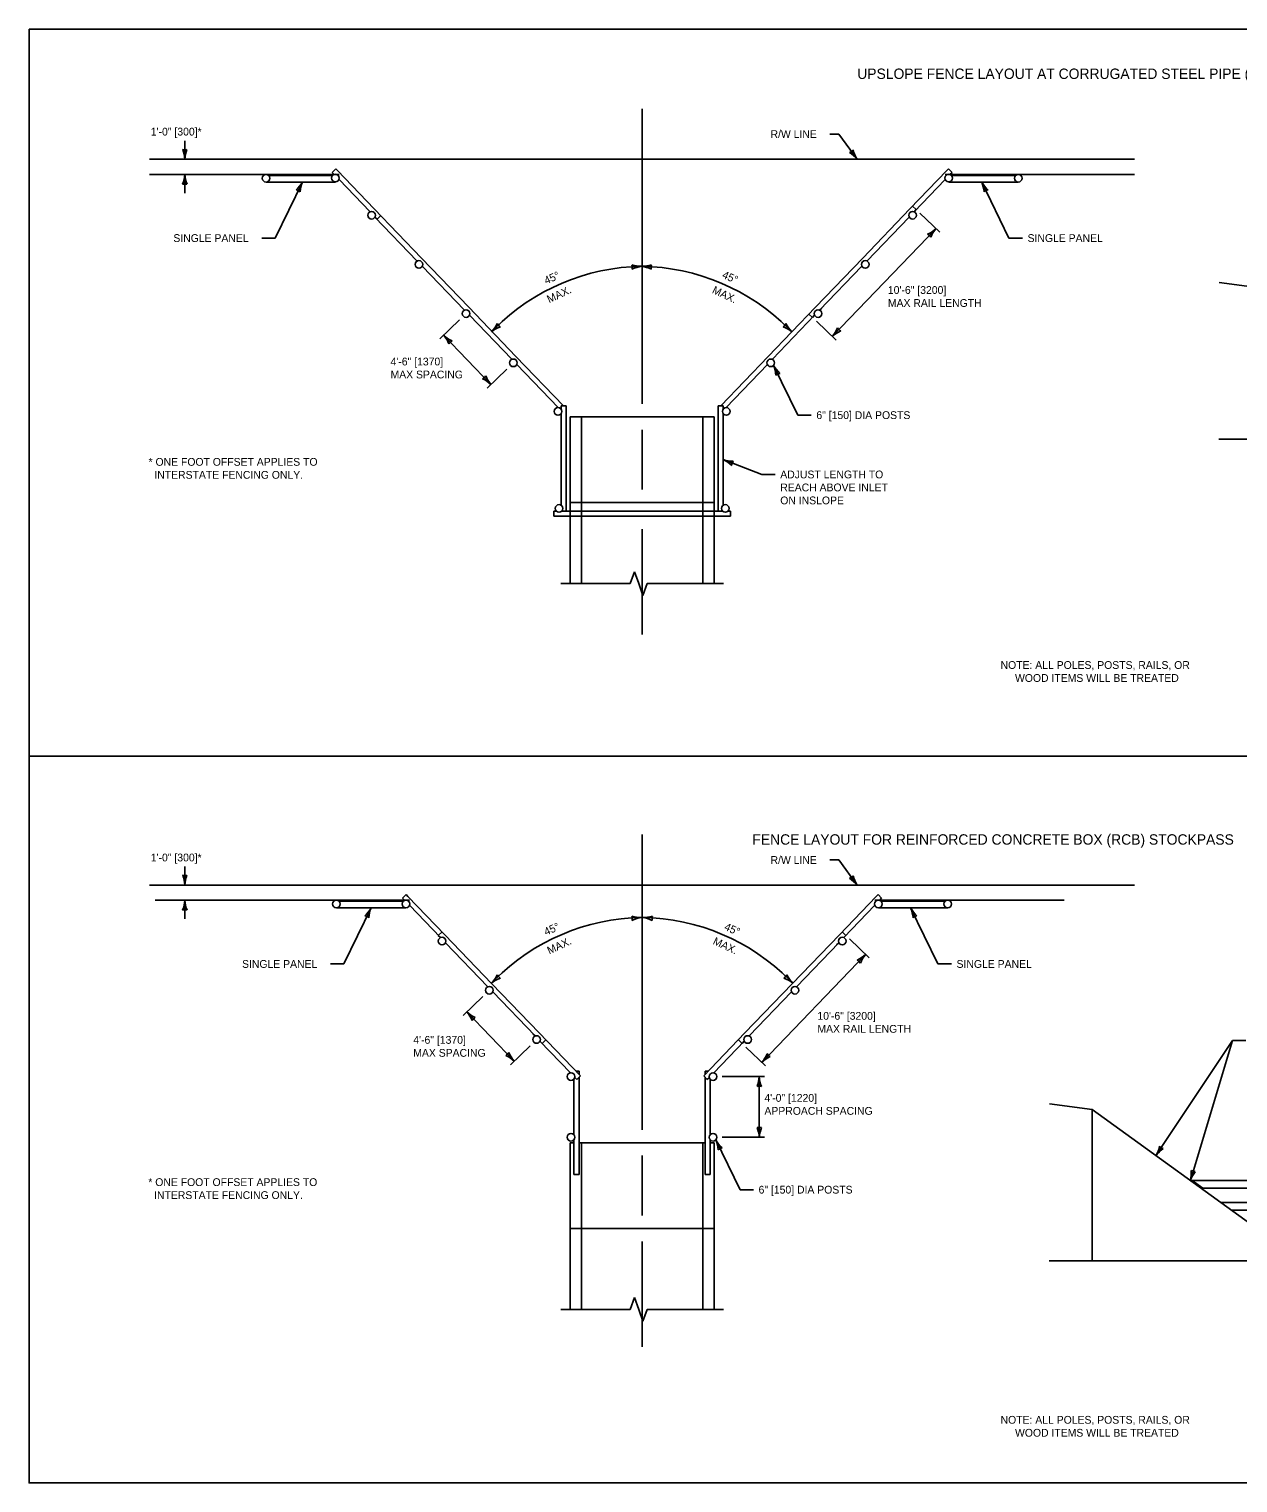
# Model space of a CAD drawing. Extents: x 49991 to 50288, y 49919 to 50011.
# Drawn here: x 49999.38 to 50008.7, y 49987.8 to 49999 of the extents above; entities that cross this region are included whole.
import ezdxf

# ---------------------------------------------------------------- set-up
doc = ezdxf.new("R2010")
doc.units = 0
for name, color, linetype in [('Level 1', 7, 'Continuous'), ('Level 2', 7, 'Continuous'), ('Level 3', 7, 'Continuous'), ('Level 5', 7, 'Continuous'), ('Level 6', 7, 'Continuous'), ('Level 7', 7, 'Continuous')]:
    doc.layers.add(name, color=color, linetype=linetype)

msp = doc.modelspace()

# ---------------------------------------------------------------- linework, layer by layer
at = {"layer": 'Level 1'}
for p, q in [((50000.311, 49997.996), (50007.9, 49997.996)), ((50000.311, 49997.879), (50001.771, 49997.879)), ((50001.209, 49997.821), (50001.743, 49997.821)), ((50001.228, 49997.872), (50001.723, 49997.872)), ((50007.9, 49997.879), (50006.441, 49997.879)), ((50006.441, 49997.879), (50006.441, 49997.879)), ((50007.003, 49997.821), (50006.468, 49997.821)), ((50006.983, 49997.872), (50006.488, 49997.872)), ((50003.639, 49996.011), (50003.551, 49996.011)), ((50003.551, 49996.011), (50003.551, 49995.975)), ((50003.639, 49996.011), (50003.639, 49994.727)), ((50003.639, 49996.011), (50004.573, 49996.011)), ((50004.573, 49996.011), (50004.573, 49994.727)), ((50004.573, 49996.011), (50004.66, 49996.011)), ((50004.66, 49996.011), (50004.66, 49995.975)), ((50003.551, 49995.975), (50003.551, 49994.727)), ((50004.66, 49995.975), (50004.66, 49994.727)), ((50010.401, 49995.839), (50008.548, 49995.839)), ((50003.551, 49995.351), (50004.66, 49995.351)), ((49999.384, 49993.399), (50016.75, 49993.399)), ((50000.311, 49992.404), (50007.9, 49992.404)), ((50000.356, 49992.288), (50002.313, 49992.288)), ((50001.751, 49992.229), (50002.286, 49992.229)), ((50001.771, 49992.281), (50002.266, 49992.281)), ((50002.313, 49992.288), (50002.313, 49992.288)), ((50007.358, 49992.288), (50005.898, 49992.288)), ((50005.898, 49992.288), (50005.898, 49992.288)), ((50006.46, 49992.229), (50005.926, 49992.229)), ((50006.441, 49992.281), (50005.945, 49992.281)), ((50008.916, 49989.704), (50007.573, 49990.676)), ((50007.573, 49990.676), (50007.573, 49989.511)), ((50003.551, 49990.42), (50003.551, 49990.383)), ((50003.551, 49990.42), (50003.551, 49990.383)), ((50003.581, 49990.42), (50003.551, 49990.42)), ((50003.581, 49990.42), (50003.551, 49990.42)), ((50003.639, 49990.42), (50003.62, 49990.42)), ((50003.639, 49990.42), (50003.62, 49990.42)), ((50003.639, 49990.42), (50003.639, 49989.135)), ((50003.639, 49990.42), (50004.573, 49990.42)), ((50004.573, 49990.42), (50004.573, 49989.135)), ((50004.573, 49990.42), (50004.591, 49990.42)), ((50004.631, 49990.42), (50004.66, 49990.42)), ((50004.66, 49990.42), (50004.66, 49990.383)), ((50003.551, 49990.383), (50003.551, 49989.135)), ((50004.66, 49990.383), (50004.66, 49989.135)), ((50003.551, 49989.759), (50004.66, 49989.759)), ((50009.095, 49989.511), (50007.242, 49989.511))]:
    msp.add_line(p, q, dxfattribs=at)
msp.add_lwpolyline([(49999.384, 49998.999), (50016.75, 49998.999), (50016.75, 49987.799), (49999.384, 49987.799)], close=True, dxfattribs=at)
msp.add_lwpolyline([(49999.384, 49998.999), (50016.75, 49998.999), (50016.75, 49987.799), (49999.384, 49987.799)], close=True, dxfattribs=at)
at = {"layer": 'Level 3'}
for p, q in [((50000.583, 49997.996), (50000.583, 49998.139)), ((50005.622, 49998.19), (50005.553, 49998.19)), ((50005.762, 49997.996), (50005.622, 49998.19)), ((50000.583, 49997.736), (50000.583, 49997.879)), ((50001.49, 49997.821), (50001.279, 49997.389)), ((50006.722, 49997.821), (50006.932, 49997.389)), ((50006.245, 49997.582), (50006.399, 49997.435)), ((50001.279, 49997.389), (50001.176, 49997.389)), ((50005.571, 49996.631), (50006.37, 49997.462)), ((50006.932, 49997.389), (50007.035, 49997.389)), ((50002.7, 49996.759), (50002.548, 49996.613)), ((50005.448, 49996.749), (50005.6, 49996.603)), ((50002.941, 49996.262), (50002.577, 49996.641)), ((50003.064, 49996.38), (50002.912, 49996.234)), ((50005.119, 49996.408), (50005.305, 49996.025)), ((50005.305, 49996.025), (50005.408, 49996.025)), ((50004.731, 49995.682), (50005.027, 49995.568)), ((50005.027, 49995.568), (50005.13, 49995.568)), ((50000.583, 49992.404), (50000.583, 49992.547)), ((50005.622, 49992.598), (50005.553, 49992.598)), ((50005.622, 49992.598), (50005.553, 49992.598)), ((50005.762, 49992.404), (50005.622, 49992.598)), ((50005.762, 49992.404), (50005.622, 49992.598)), ((50000.583, 49992.145), (50000.583, 49992.288)), ((50002.019, 49992.229), (50001.808, 49991.797)), ((50006.174, 49992.229), (50006.385, 49991.797)), ((50005.703, 49991.99), (50005.856, 49991.843)), ((50005.028, 49991.039), (50005.827, 49991.871)), ((50001.808, 49991.797), (50001.705, 49991.797)), ((50006.385, 49991.797), (50006.488, 49991.797)), ((50002.879, 49991.546), (50002.727, 49991.4)), ((50003.12, 49991.049), (50002.756, 49991.428)), ((50008.064, 49990.321), (50008.653, 49991.206)), ((50008.329, 49990.129), (50008.653, 49991.206)), ((50008.653, 49991.206), (50008.756, 49991.206)), ((50003.243, 49991.167), (50003.091, 49991.021)), ((50004.905, 49991.157), (50005.057, 49991.011)), ((50004.723, 49990.929), (50005.048, 49990.929)), ((50005.008, 49990.462), (50005.008, 49990.929)), ((50004.674, 49990.441), (50004.86, 49990.058)), ((50004.723, 49990.462), (50005.048, 49990.462)), ((50004.86, 49990.058), (50004.963, 49990.058))]:
    msp.add_line(p, q, dxfattribs=at)
for centre, radius, start, end in [((50000.583, 49998.124), 0.0548, 252.1388, 287.8612), ((50000.351, 49997.985), 0.233, 2.8273, 22.0772), ((50000.805, 49997.987), 0.222, 157.456, 177.6395), ((50005.687, 49998.1), 0.0548, 287.6554, 323.3778), ((50005.579, 49997.852), 0.233, 38.3439, 57.5938), ((50005.948, 49998.118), 0.222, 192.9726, 213.1561), ((50000.361, 49997.889), 0.222, 337.456, 357.6395), ((50000.583, 49997.751), 0.0548, 72.1388, 107.8612), ((50000.816, 49997.891), 0.233, 182.8273, 202.0772), ((50001.285, 49997.933), 0.233, 311.9873, 331.2371), ((50001.693, 49997.732), 0.222, 156.4249, 176.6084), ((50006.518, 49997.732), 0.222, 3.3916, 23.5751), ((50006.926, 49997.933), 0.233, 208.7629, 228.0127), ((50001.434, 49997.706), 0.0548, 46.2033, 81.9256), ((50006.778, 49997.706), 0.0548, 98.0744, 133.7967), ((50006.21, 49997.632), 0.233, 294.0637, 313.3135), ((50006.281, 49997.37), 0.0548, 28.2797, 64.002), ((50006.536, 49997.315), 0.222, 138.5013, 158.6848), ((50004.129, 49995.534), 1.638, 90.9235, 135.0582), ((50003.975, 49997.162), 0.0548, 346.4057, 22.1281), ((50004.097, 49997.405), 0.233, 252.1897, 271.4396), ((50004.128, 49996.951), 0.222, 96.6274, 116.8109), ((50004.108, 49997.405), 0.233, 268.5604, 287.8103), ((50004.077, 49996.951), 0.222, 63.1891, 83.3726), ((50004.076, 49995.534), 1.638, 44.9418, 89.0765), ((50004.23, 49997.162), 0.0548, 157.8719, 193.5943), ((50002.79, 49996.826), 0.222, 314.3336, 334.5171), ((50003.093, 49996.486), 0.233, 109.8959, 129.1458), ((50003.041, 49996.753), 0.0548, 204.1119, 239.8343), ((50005.164, 49996.753), 0.0548, 300.1657, 335.8881), ((50005.112, 49996.486), 0.233, 50.8542, 70.1041), ((50005.414, 49996.826), 0.222, 205.4829, 225.6664), ((50005.404, 49996.778), 0.222, 318.5013, 338.6848), ((50005.66, 49996.723), 0.0548, 208.2797, 244.002), ((50002.411, 49996.493), 0.222, 21.3152, 41.4987), ((50002.737, 49996.81), 0.233, 226.6865, 245.9363), ((50002.666, 49996.548), 0.0548, 115.998, 151.7203), ((50005.731, 49996.461), 0.233, 114.0637, 133.3135), ((50004.915, 49996.319), 0.222, 3.3916, 23.5751), ((50005.323, 49996.52), 0.233, 208.7629, 228.0127), ((50005.175, 49996.292), 0.0548, 98.0744, 133.7967), ((50002.852, 49996.354), 0.0548, 295.998, 331.7203), ((50002.781, 49996.092), 0.233, 46.6865, 65.9363), ((50003.108, 49996.409), 0.222, 201.3152, 221.4987), ((50004.643, 49995.477), 0.222, 46.4346, 66.6181), ((50004.804, 49995.903), 0.233, 251.8059, 271.0558), ((50004.851, 49995.636), 0.0548, 141.1174, 176.8398), ((50000.583, 49992.533), 0.0548, 252.1388, 287.8612), ((50000.351, 49992.393), 0.233, 2.8273, 22.0772), ((50000.805, 49992.395), 0.222, 157.456, 177.6395), ((50005.687, 49992.509), 0.0548, 287.6554, 323.3778), ((50005.687, 49992.509), 0.0548, 287.6554, 323.3778), ((50005.579, 49992.26), 0.233, 38.3439, 57.5938), ((50005.579, 49992.26), 0.233, 38.3439, 57.5938), ((50005.948, 49992.526), 0.222, 192.9726, 213.1561), ((50005.948, 49992.526), 0.222, 192.9726, 213.1561), ((50000.361, 49992.297), 0.222, 337.456, 357.6395), ((50000.583, 49992.159), 0.0548, 72.1388, 107.8612), ((50000.816, 49992.299), 0.233, 182.8273, 202.0772), ((50001.814, 49992.341), 0.233, 311.9873, 331.2371), ((50002.222, 49992.14), 0.222, 156.4249, 176.6084), ((50005.971, 49992.14), 0.222, 3.3916, 23.5751), ((50006.379, 49992.341), 0.233, 208.7629, 228.0127), ((50001.962, 49992.114), 0.0548, 46.2033, 81.9256), ((50004.129, 49990.517), 1.638, 90.9235, 135.0582), ((50003.975, 49992.145), 0.0548, 346.4057, 22.1281), ((50004.097, 49992.388), 0.233, 252.1897, 271.4396), ((50004.128, 49991.934), 0.222, 96.6274, 116.8109), ((50004.115, 49992.388), 0.233, 268.5604, 287.8103), ((50004.083, 49990.517), 1.638, 44.9418, 89.0765), ((50004.083, 49991.934), 0.222, 63.1891, 83.3726), ((50004.237, 49992.145), 0.0548, 157.8719, 193.5943), ((50006.23, 49992.114), 0.0548, 98.0744, 133.7967), ((50005.667, 49992.04), 0.233, 294.0637, 313.3135), ((50005.994, 49991.723), 0.222, 138.5013, 158.6848), ((50005.738, 49991.778), 0.0548, 28.2797, 64.002), ((50002.79, 49991.809), 0.222, 314.3336, 334.5171), ((50003.093, 49991.469), 0.233, 109.8959, 129.1458), ((50003.041, 49991.736), 0.0548, 204.1119, 239.8343), ((50005.17, 49991.736), 0.0548, 300.1657, 335.8881), ((50005.119, 49991.469), 0.233, 50.8542, 70.1041), ((50005.421, 49991.809), 0.222, 205.4829, 225.6664), ((50002.589, 49991.28), 0.222, 21.3152, 41.4987), ((50002.916, 49991.597), 0.233, 226.6865, 245.9363), ((50002.845, 49991.335), 0.0548, 115.998, 151.7203), ((50003.031, 49991.141), 0.0548, 295.998, 331.7203), ((50002.96, 49990.879), 0.233, 46.6865, 65.9363), ((50003.286, 49991.196), 0.222, 201.3152, 221.4987), ((50004.862, 49991.186), 0.222, 318.5013, 338.6848), ((50005.188, 49990.87), 0.233, 114.0637, 133.3135), ((50005.117, 49991.132), 0.0548, 208.2797, 244.002), ((50004.786, 49990.938), 0.222, 337.456, 357.6395), ((50005.241, 49990.94), 0.233, 182.8273, 202.0772), ((50005.008, 49990.801), 0.0548, 72.1388, 107.8612), ((50005.008, 49990.59), 0.0548, 252.1388, 287.8612), ((50004.776, 49990.45), 0.233, 2.8273, 22.0772), ((50005.231, 49990.453), 0.222, 157.456, 177.6395), ((50004.47, 49990.352), 0.222, 3.3916, 23.5751), ((50004.878, 49990.553), 0.233, 208.7629, 228.0127), ((50004.73, 49990.326), 0.0548, 98.0744, 133.7967), ((50007.864, 49990.44), 0.233, 329.1652, 348.415), ((50008.244, 49990.19), 0.222, 123.7939, 143.9774), ((50008.135, 49990.427), 0.0548, 218.4767, 254.199), ((50008.103, 49990.185), 0.233, 346.0815, 5.3313), ((50008.539, 49990.056), 0.222, 140.7102, 160.8937), ((50008.366, 49990.252), 0.0548, 235.393, 271.1153)]:
    msp.add_arc(centre, radius, start, end, dxfattribs=at)
at = {"layer": 'Level 5'}
for p, q in [((50004.106, 49996.111), (50004.106, 49998.385)), ((50008.879, 49997.003), (50008.551, 49997.048)), ((50004.106, 49995.451), (50004.106, 49995.911)), ((50004.106, 49994.335), (50004.106, 49995.146)), ((50004.106, 49990.52), (50004.106, 49992.794)), ((50007.573, 49990.676), (50007.245, 49990.72)), ((50004.106, 49989.859), (50004.106, 49990.32)), ((50004.106, 49988.848), (50004.106, 49989.659))]:
    msp.add_line(p, q, dxfattribs=at)
at = {"layer": 'Level 6'}
for p, q in [((50004.015, 49994.727), (50004.048, 49994.818)), ((50004.08, 49994.727), (50004.048, 49994.818)), ((50003.48, 49994.727), (50004.015, 49994.727)), ((50004.112, 49994.636), (50004.08, 49994.727)), ((50004.112, 49994.636), (50004.145, 49994.727)), ((50004.732, 49994.727), (50004.145, 49994.727)), ((50004.015, 49989.135), (50004.048, 49989.227)), ((50004.08, 49989.135), (50004.048, 49989.227)), ((50003.48, 49989.135), (50004.015, 49989.135)), ((50004.112, 49989.044), (50004.08, 49989.135)), ((50004.112, 49989.044), (50004.145, 49989.135)), ((50004.732, 49989.135), (50004.145, 49989.135))]:
    msp.add_line(p, q, dxfattribs=at)
at = {"layer": 'Level 7'}
for p, q in [((50001.718, 49997.895), (50001.746, 49997.922)), ((50001.746, 49997.922), (50001.759, 49997.909)), ((50006.465, 49997.922), (50006.452, 49997.909)), ((50006.494, 49997.895), (50006.465, 49997.922)), ((50001.734, 49997.878), (50001.718, 49997.895)), ((50001.759, 49997.909), (50002.042, 49997.614)), ((50001.771, 49997.84), (50002.01, 49997.591)), ((50006.452, 49997.909), (50006.169, 49997.614)), ((50006.441, 49997.84), (50006.202, 49997.591)), ((50006.477, 49997.878), (50006.494, 49997.895)), ((50002.042, 49997.614), (50002.406, 49997.235)), ((50006.169, 49997.614), (50005.805, 49997.235)), ((50006.218, 49997.608), (50006.189, 49997.635)), ((50006.202, 49997.591), (50006.218, 49997.608)), ((50002.048, 49997.551), (50002.374, 49997.212)), ((50002.048, 49997.551), (50002.064, 49997.535)), ((50002.064, 49997.535), (50002.093, 49997.562)), ((50006.163, 49997.551), (50005.837, 49997.212)), ((50006.163, 49997.551), (50006.147, 49997.535)), ((50002.406, 49997.235), (50002.77, 49996.857)), ((50002.412, 49997.173), (50002.738, 49996.834)), ((50005.805, 49997.235), (50005.441, 49996.857)), ((50005.799, 49997.173), (50005.473, 49996.834)), ((50002.77, 49996.857), (50003.134, 49996.478)), ((50002.776, 49996.794), (50003.102, 49996.455)), ((50005.441, 49996.857), (50005.077, 49996.478)), ((50005.435, 49996.794), (50005.109, 49996.455)), ((50005.419, 49996.777), (50005.391, 49996.804)), ((50005.435, 49996.794), (50005.419, 49996.777)), ((50005.473, 49996.834), (50005.49, 49996.85)), ((50003.134, 49996.478), (50003.501, 49996.096)), ((50005.077, 49996.478), (50004.711, 49996.096)), ((50003.14, 49996.415), (50003.458, 49996.084)), ((50005.071, 49996.415), (50004.753, 49996.084)), ((50003.52, 49996.096), (50003.481, 49996.096)), ((50003.481, 49996.096), (50003.481, 49996.072)), ((50003.481, 49995.328), (50003.481, 49996.035)), ((50003.52, 49995.286), (50003.52, 49996.096)), ((50004.692, 49995.286), (50004.692, 49996.096)), ((50004.692, 49996.096), (50004.731, 49996.096)), ((50004.731, 49996.096), (50004.731, 49996.072)), ((50004.731, 49995.328), (50004.731, 49996.035)), ((50003.445, 49995.286), (50003.425, 49995.286)), ((50003.425, 49995.286), (50003.425, 49995.246)), ((50003.425, 49995.246), (50004.662, 49995.246)), ((50003.487, 49995.286), (50004.696, 49995.286)), ((50004.725, 49995.286), (50003.515, 49995.286)), ((50004.787, 49995.246), (50003.549, 49995.246)), ((50004.766, 49995.286), (50004.787, 49995.286)), ((50004.787, 49995.286), (50004.787, 49995.246)), ((50002.261, 49992.304), (50002.289, 49992.331)), ((50002.289, 49992.331), (50002.302, 49992.317)), ((50002.302, 49992.317), (50002.585, 49992.022)), ((50005.91, 49992.317), (50005.626, 49992.022)), ((50005.923, 49992.331), (50005.91, 49992.317)), ((50005.951, 49992.304), (50005.923, 49992.331)), ((50002.277, 49992.287), (50002.261, 49992.304)), ((50002.313, 49992.249), (50002.553, 49992)), ((50005.898, 49992.249), (50005.659, 49992)), ((50005.935, 49992.287), (50005.951, 49992.304)), ((50002.536, 49992.016), (50002.565, 49992.044)), ((50002.553, 49992), (50002.536, 49992.016)), ((50002.585, 49992.022), (50002.949, 49991.644)), ((50005.626, 49992.022), (50005.262, 49991.644)), ((50005.675, 49992.016), (50005.647, 49992.044)), ((50005.659, 49992), (50005.675, 49992.016)), ((50002.591, 49991.96), (50002.917, 49991.621)), ((50002.591, 49991.96), (50002.607, 49991.943)), ((50005.62, 49991.96), (50005.295, 49991.621)), ((50005.62, 49991.96), (50005.604, 49991.943)), ((50002.949, 49991.644), (50003.313, 49991.265)), ((50005.262, 49991.644), (50004.898, 49991.265)), ((50002.955, 49991.581), (50003.281, 49991.242)), ((50005.256, 49991.581), (50004.931, 49991.242)), ((50003.281, 49991.242), (50003.265, 49991.259)), ((50003.313, 49991.265), (50003.631, 49990.934)), ((50003.319, 49991.202), (50003.554, 49990.958)), ((50003.319, 49991.202), (50003.335, 49991.185)), ((50003.335, 49991.185), (50003.364, 49991.212)), ((50004.898, 49991.265), (50004.58, 49990.934)), ((50004.892, 49991.202), (50004.658, 49990.958)), ((50004.876, 49991.185), (50004.848, 49991.212)), ((50004.892, 49991.202), (50004.876, 49991.185)), ((50004.931, 49991.242), (50004.947, 49991.259)), ((50003.62, 49990.972), (50003.595, 49990.972)), ((50003.62, 49990.945), (50003.62, 49990.972)), ((50004.591, 49990.972), (50004.617, 49990.972)), ((50004.591, 49990.945), (50004.591, 49990.972)), ((50003.581, 49990.91), (50003.581, 49990.481)), ((50003.587, 49990.923), (50003.603, 49990.906)), ((50003.603, 49990.906), (50003.631, 49990.934)), ((50003.62, 49990.175), (50003.62, 49990.923)), ((50004.608, 49990.906), (50004.58, 49990.934)), ((50004.591, 49990.175), (50004.591, 49990.923)), ((50004.625, 49990.923), (50004.608, 49990.906)), ((50004.631, 49990.91), (50004.631, 49990.481)), ((50003.581, 49990.175), (50003.581, 49990.443)), ((50004.631, 49990.175), (50004.631, 49990.443)), ((50003.62, 49990.175), (50003.581, 49990.175)), ((50004.591, 49990.175), (50004.631, 49990.175)), ((50008.329, 49990.129), (50010.004, 49990.129)), ((50008.329, 49990.129), (50008.344, 49990.129)), ((50008.425, 49990.07), (50008.344, 49990.129)), ((50010.004, 49990.07), (50008.411, 49990.07)), ((50008.411, 49990.07), (50008.425, 49990.07)), ((50008.563, 49989.96), (50010.004, 49989.96)), ((50010.004, 49989.901), (50008.644, 49989.901))]:
    msp.add_line(p, q, dxfattribs=at)
for centre in [(50001.209, 49997.85), (50001.743, 49997.851), (50006.468, 49997.851), (50007.003, 49997.85), (50002.022, 49997.565), (50006.189, 49997.565), (50002.386, 49997.186), (50005.825, 49997.186), (50002.75, 49996.807), (50005.461, 49996.807), (50003.114, 49996.428), (50005.097, 49996.428), (50003.458, 49996.054), (50004.754, 49996.054), (50003.466, 49995.306), (50004.746, 49995.306), (50001.751, 49992.259), (50002.286, 49992.259), (50005.926, 49992.259), (50006.46, 49992.259), (50002.565, 49991.973), (50005.647, 49991.973), (50002.929, 49991.594), (50005.283, 49991.594), (50003.293, 49991.215), (50004.919, 49991.215), (50003.558, 49990.929), (50004.653, 49990.929), (50003.558, 49990.462), (50004.653, 49990.462)]:
    msp.add_circle(centre, 0.0294, dxfattribs=at)

# ---------------------------------------------------------------- texts
at = {"layer": 'Level 2'}
for s, height, p in [('UPSLOPE FENCE LAYOUT AT CORRUGATED STEEL PIPE (CSP) STOCKPASS', 0.08, (50005.763, 49998.615)), ('1\'-0" [300]*', 0.06, (50000.321, 49998.179)), ('R/W LINE', 0.06, (50005.095, 49998.16)), ('SINGLE PANEL', 0.06, (50000.495, 49997.359)), ('SINGLE PANEL', 0.06, (50007.075, 49997.359)), ('10\'-6" [3200]', 0.06, (50005.999, 49996.959)), ('MAX RAIL LENGTH', 0.06, (50005.999, 49996.859)), ('4\'-6" [1370]', 0.06, (50002.168, 49996.408)), ('MAX SPACING', 0.06, (50002.168, 49996.308)), ('6" [150] DIA POSTS', 0.06, (50005.448, 49995.995)), ('* ONE FOOT OFFSET APPLIES TO', 0.06, (50000.304, 49995.635)), ('  INTERSTATE FENCING ONLY.', 0.06, (50000.304, 49995.535)), ('ADJUST LENGTH TO', 0.06, (50005.17, 49995.538)), ('REACH ABOVE INLET', 0.06, (50005.17, 49995.438)), ('ON INSLOPE', 0.06, (50005.17, 49995.338)), ('NOTE: ALL POLES, POSTS, RAILS, OR ', 0.06, (50006.867, 49994.07)), ('     WOOD ITEMS WILL BE TREATED', 0.06, (50006.867, 49993.97)), ('FENCE LAYOUT FOR REINFORCED CONCRETE BOX (RCB) STOCKPASS', 0.08, (50004.955, 49992.716)), ('1\'-0" [300]*', 0.06, (50000.321, 49992.587)), ('R/W LINE', 0.06, (50005.095, 49992.568)), ('SINGLE PANEL', 0.06, (50001.024, 49991.767)), ('SINGLE PANEL', 0.06, (50006.528, 49991.767)), ('10\'-6" [3200]', 0.06, (50005.456, 49991.367)), ('MAX RAIL LENGTH', 0.06, (50005.456, 49991.267)), ('4\'-6" [1370]', 0.06, (50002.343, 49991.182)), ('MAX SPACING', 0.06, (50002.343, 49991.082)), ('4\'-0" [1220]', 0.06, (50005.048, 49990.735)), ('APPROACH SPACING', 0.06, (50005.048, 49990.635)), ('* ONE FOOT OFFSET APPLIES TO', 0.06, (50000.302, 49990.086)), ('6" [150] DIA POSTS', 0.06, (50005.003, 49990.028)), ('  INTERSTATE FENCING ONLY.', 0.06, (50000.302, 49989.986)), ('NOTE: ALL POLES, POSTS, RAILS, OR ', 0.06, (50006.867, 49988.255)), ('     WOOD ITEMS WILL BE TREATED', 0.06, (50006.867, 49988.155))]:
    msp.add_text(s, height=height, dxfattribs=at).set_placement(p)
for s, rotation, p in [('45°', 24.0137, (50003.367, 49997.031)), ('MAX.', 335.0081, (50004.64, 49996.968)), ('45°', 335.9863, (50004.717, 49997.085)), ('MAX.', 24.9919, (50003.39, 49996.887)), ('45°', 24.0137, (50003.366, 49992.014)), ('45°', 335.9863, (50004.733, 49992.062)), ('MAX.', 24.9919, (50003.391, 49991.87)), ('MAX.', 335.0081, (50004.646, 49991.952))]:
    msp.add_text(s, height=0.06, rotation=rotation, dxfattribs=at).set_placement(p)

doc.saveas('drawing.dxf')
